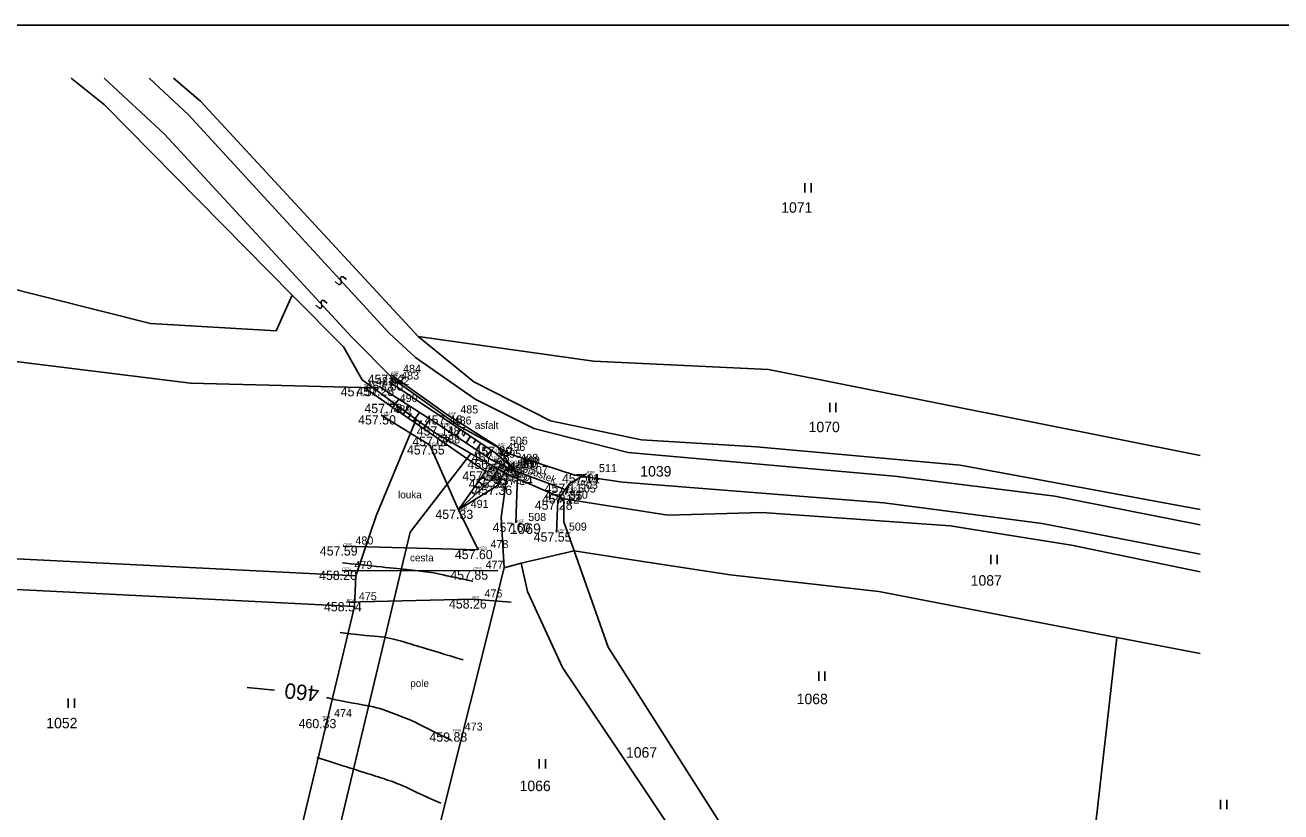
# Model space of a CAD drawing. Extents: x -604848 to -603227, y -1111879 to -1109838.
# Drawn here: x -603616.4 to -603412.5, y -1109965.7 to -1109837.9 of the extents above; entities that cross this region are included whole.
import ezdxf

# ---------------------------------------------------------------- set-up
doc = ezdxf.new("R2010")
doc.units = 0
for name, color, linetype in [('1', 7, 'Continuous'), ('10', 7, 'Continuous'), ('14', 7, 'Continuous'), ('18', 7, 'Continuous'), ('19', 7, 'Continuous'), ('2', 7, 'Continuous'), ('20', 7, 'Continuous'), ('23', 7, 'Continuous'), ('4', 7, 'Continuous'), ('7', 7, 'Continuous'), ('8', 7, 'Continuous'), ('9', 7, 'Continuous'), ('Default', 7, 'Continuous')]:
    doc.layers.add(name, color=color, linetype=linetype)

# ---------------------------------------------------------------- blocks, each defined once
blk = doc.blocks.new('Z3060')
at = {"layer": '23'}
for p, q in [((-0.5, 0), (-0.5, 1.5)), ((0.5, 1.5), (0.5, 0))]:
    blk.add_line(p, q, dxfattribs=at)
blk = doc.blocks.new('POINT_DISPLAY')
at = {"layer": 'Default'}
blk.add_line((0, 0), (0, 0), dxfattribs=at)
blk = doc.blocks.new('Z218')
at = {"layer": '2'}
for p, q in [((-0.2, 0.7), (-0.4, 0.5)), ((-0.4, 0.5), (-0.4, 0.3)), ((-0.4, 0.3), (-0.2, 0.1)), ((0.5, 0.8), (-0.2, 0.7)), ((-0.2, 0.1), (0.2, -0.1)), ((0.2, -0.7), (-0.5, -0.8)), ((0.2, -0.1), (0.4, -0.3)), ((0.4, -0.5), (0.2, -0.7)), ((0.4, -0.3), (0.4, -0.5))]:
    blk.add_line(p, q, dxfattribs=at)

msp = doc.modelspace()

# ---------------------------------------------------------------- linework, layer by layer
at = {"layer": '1'}
for p, q in [((-603603.52, -1109850.88), (-603608.9, -1109846.55)), ((-603592.28, -1109846.55), (-603587.91, -1109850.29)), ((-603573.01, -1109881.76), (-603603.52, -1109850.88)), ((-603587.91, -1109850.29), (-603552.55, -1109888.51)), ((-603633.29, -1109877.02), (-603596.04, -1109886.41)), ((-603575.63, -1109887.55), (-603573.01, -1109881.76)), ((-603564.71, -1109890.15), (-603573.01, -1109881.76)), ((-603589.52, -1109896.09), (-603686.95, -1109884.04)), ((-603596.04, -1109886.41), (-603575.63, -1109887.55)), ((-603561.66, -1109895.54), (-603564.71, -1109890.15)), ((-603552.55, -1109888.51), (-603524.1, -1109892.48)), ((-603543.5, -1109895.84), (-603552.55, -1109888.51)), ((-603524.1, -1109892.48), (-603495.66, -1109893.88)), ((-603495.66, -1109893.88), (-603425.58, -1109907.82)), ((-603559.88, -1109896.84), (-603589.52, -1109896.09)), ((-603559.88, -1109896.84), (-603561.66, -1109895.54)), ((-603531.07, -1109902.2), (-603543.5, -1109895.84)), ((-603552.87, -1109901.95), (-603559.88, -1109896.84)), ((-603559.39, -1109917.61), (-603552.87, -1109901.95)), ((-603549.91, -1109904.11), (-603552.87, -1109901.95)), ((-603516.27, -1109905.3), (-603531.07, -1109902.2)), ((-603544.01, -1109907.48), (-603549.91, -1109904.11)), ((-603497.64, -1109906.42), (-603516.27, -1109905.3)), ((-603464.54, -1109909.38), (-603497.64, -1109906.42)), ((-603553.85, -1109920.25), (-603544.01, -1109907.48)), ((-603544.01, -1109907.48), (-603538.11, -1109910.84)), ((-603425.58, -1109916.59), (-603464.54, -1109909.38)), ((-603538.11, -1109910.84), (-603539.09, -1109917.87)), ((-603538.11, -1109910.84), (-603528.91, -1109914.84)), ((-603512.03, -1109917.53), (-603528.91, -1109914.84)), ((-603528.91, -1109914.84), (-603528.91, -1109918.57)), ((-603562.66, -1109927.35), (-603559.39, -1109917.61)), ((-603539.09, -1109917.87), (-603538.61, -1109926.08)), ((-603528.91, -1109918.57), (-603527.23, -1109923.32)), ((-603496.72, -1109917.08), (-603512.03, -1109917.53)), ((-603466.14, -1109919.25), (-603496.72, -1109917.08)), ((-603575.13, -1110009.26), (-603553.85, -1109920.25)), ((-603446.47, -1109922.37), (-603466.14, -1109919.25)), ((-603425.58, -1109926.71), (-603446.47, -1109922.37)), ((-603648.55, -1109923.04), (-603562.66, -1109927.35)), ((-603535.85, -1109925.28), (-603527.23, -1109923.32)), ((-603527.23, -1109923.32), (-603519.62, -1109924.48)), ((-603527.23, -1109923.32), (-603521.7, -1109938.92)), ((-603519.62, -1109924.48), (-603501.91, -1109927.22)), ((-603550.44, -1109973.35), (-603538.61, -1109926.08)), ((-603538.61, -1109926.08), (-603535.85, -1109925.28)), ((-603534.83, -1109929.91), (-603535.85, -1109925.28)), ((-603648.86, -1109928.03), (-603562.91, -1109932.34)), ((-603562.66, -1109927.35), (-603562.91, -1109932.34)), ((-603501.91, -1109927.22), (-603477.74, -1109929.92)), ((-603529.1, -1109942.23), (-603534.83, -1109929.91)), ((-603477.74, -1109929.92), (-603439.12, -1109937.35)), ((-603562.91, -1109932.34), (-603571.51, -1109968.22)), ((-603521.7, -1109938.92), (-603496.72, -1109978.18)), ((-603439.12, -1109937.35), (-603445.06, -1109990.31)), ((-603425.58, -1109939.95), (-603439.12, -1109937.35)), ((-603515.89, -1109961.92), (-603529.1, -1109942.23)), ((-603502.69, -1109981.6), (-603515.89, -1109961.92))]:
    msp.add_line(p, q, dxfattribs=at)
msp.add_lwpolyline([(-603227.31, -1110677.93), (-603227.31, -1109837.93), (-603821.31, -1109837.93), (-603821.31, -1110677.93), (-603227.31, -1110677.93)], dxfattribs=at)
at = {"layer": '10'}
for p, q in [((-603558.56, -1109901.28), (-603550.66, -1109906.16)), ((-603550.66, -1109906.16), (-603546.03, -1109916.62)), ((-603546.03, -1109916.62), (-603542.81, -1109923.15)), ((-603543.79, -1109931.17), (-603564.19, -1109931.63)), ((-603543.79, -1109931.17), (-603537.46, -1109931.61))]:
    msp.add_line(p, q, dxfattribs=at)
at = {"layer": '2'}
for p, q in [((-603603.53, -1109846.55), (-603593.75, -1109855.63)), ((-603589.87, -1109852.5), (-603596.24, -1109846.55)), ((-603557.27, -1109887.93), (-603589.87, -1109852.5)), ((-603593.75, -1109855.63), (-603563.39, -1109888.55)), ((-603553.01, -1109891.89), (-603557.27, -1109887.93)), ((-603563.39, -1109888.55), (-603556.56, -1109895.4)), ((-603543.29, -1109898.66), (-603553.01, -1109891.89)), ((-603556.56, -1109895.4), (-603546, -1109902.98)), ((-603533.8, -1109903.43), (-603543.29, -1109898.66)), ((-603546, -1109902.98), (-603537.42, -1109907.68)), ((-603518.47, -1109907.32), (-603533.8, -1109903.43)), ((-603537.42, -1109907.68), (-603527.13, -1109911)), ((-603475.23, -1109911.19), (-603518.47, -1109907.32)), ((-603527.13, -1109911), (-603519.35, -1109912.17)), ((-603519.35, -1109912.17), (-603476.94, -1109915.52)), ((-603449.19, -1109914.4), (-603475.23, -1109911.19)), ((-603425.58, -1109919.06), (-603449.19, -1109914.4)), ((-603476.94, -1109915.52), (-603451.22, -1109918.85)), ((-603451.22, -1109918.85), (-603425.58, -1109923.86))]:
    msp.add_line(p, q, dxfattribs=at)
at = {"layer": '4'}
for p, q in [((-603547.72, -1109901.29), (-603557.01, -1109894.68)), ((-603539.67, -1109906.36), (-603547.72, -1109901.29)), ((-603536.41, -1109911.12), (-603539.67, -1109906.36)), ((-603537.97, -1109910.25), (-603538.48, -1109910.22)), ((-603537.97, -1109909.17), (-603537.68, -1109909.57)), ((-603537.68, -1109909.57), (-603537.97, -1109910.25)), ((-603537.87, -1109909.92), (-603528.27, -1109913.52)), ((-603536.68, -1109918.75), (-603536.41, -1109911.12)), ((-603529.9, -1109915.13), (-603528.03, -1109912.4)), ((-603528.63, -1109914.14), (-603528.03, -1109912.4)), ((-603528.03, -1109912.4), (-603525.2, -1109910.82)), ((-603530.08, -1109920.31), (-603529.9, -1109915.13)), ((-603542.81, -1109923.15), (-603564.75, -1109922.57)), ((-603564.91, -1109926.53), (-603543.61, -1109926.49)), ((-603543.61, -1109926.49), (-603539.6, -1109926.56))]:
    msp.add_line(p, q, dxfattribs=at)
at = {"layer": '7'}
for p, q in [((-603557.32, -1109895.78), (-603540.06, -1109907.38)), ((-603557.55, -1109899.43), (-603561.4, -1109896.7)), ((-603558.88, -1109896.63), (-603548.79, -1109903.09)), ((-603549.76, -1109904.78), (-603557.55, -1109899.43)), ((-603548.79, -1109903.09), (-603540.74, -1109908.49)), ((-603541.62, -1109910.41), (-603549.76, -1109904.78)), ((-603540.74, -1109908.49), (-603537.87, -1109909.92)), ((-603537.97, -1109909.17), (-603540.06, -1109907.38)), ((-603546.03, -1109916.62), (-603541.62, -1109910.41)), ((-603540.54, -1109911.64), (-603539.15, -1109909.28)), ((-603538.55, -1109910.47), (-603539.65, -1109912.71)), ((-603538.48, -1109910.22), (-603538.55, -1109910.47)), ((-603546.03, -1109916.62), (-603540.54, -1109911.64)), ((-603539.65, -1109912.71), (-603546.03, -1109916.62)), ((-603575.87, -1109945.94), (-603580.35, -1109945.5))]:
    msp.add_line(p, q, dxfattribs=at)
for points in [[(-603543.68, -1109928.2), (-603546.74, -1109927.64), (-603549.77, -1109926.84), (-603552.87, -1109926.51), (-603556.87, -1109926.09), (-603560.86, -1109925.67), (-603564.86, -1109925.25)], [(-603545.24, -1109941.01), (-603548.45, -1109940.05), (-603551.59, -1109939.08), (-603554.85, -1109938.11), (-603558.25, -1109937.1), (-603561.77, -1109937.06), (-603565.23, -1109936.54)], [(-603547.19, -1109954.02), (-603550.29, -1109952.58), (-603553.28, -1109950.92), (-603556.5, -1109949.72), (-603560.04, -1109948.41), (-603563.82, -1109948), (-603567.47, -1109947.13)], [(-603548.86, -1109964.27), (-603552.11, -1109962.9), (-603555.26, -1109961.23), (-603558.62, -1109960.16), (-603562.09, -1109959.05), (-603565.55, -1109957.95), (-603569.02, -1109956.84)]]:
    msp.add_open_spline(points, degree=3, dxfattribs=at)
at = {"layer": '8'}
for p, q in [((-603556.65, -1109900.05), (-603555.7, -1109898.66)), ((-603555.83, -1109900.62), (-603555.34, -1109899.91)), ((-603555, -1109901.18), (-603554.02, -1109899.74)), ((-603554.18, -1109901.75), (-603553.68, -1109901.02)), ((-603553.35, -1109902.31), (-603552.33, -1109900.82)), ((-603552.53, -1109902.88), (-603552.01, -1109902.12)), ((-603551.7, -1109903.45), (-603550.65, -1109901.9)), ((-603545.71, -1109903.59), (-603546.43, -1109904.67)), ((-603544.88, -1109904.15), (-603545.24, -1109904.69)), ((-603544.05, -1109904.7), (-603544.77, -1109905.78)), ((-603543.22, -1109905.26), (-603543.58, -1109905.8)), ((-603542.39, -1109905.82), (-603543.11, -1109906.9)), ((-603541.56, -1109906.38), (-603541.92, -1109906.92)), ((-603540.73, -1109906.94), (-603541.45, -1109908.01)), ((-603542.78, -1109912.04), (-603541.77, -1109912.76)), ((-603542.2, -1109911.23), (-603541.61, -1109911.65)), ((-603543.94, -1109913.67), (-603543.29, -1109914.14)), ((-603543.36, -1109912.86), (-603542.94, -1109913.15))]:
    msp.add_line(p, q, dxfattribs=at)

# ---------------------------------------------------------------- block references
at = {"layer": '18'}
for p in [(-603557.32, -1109895.78), (-603557.01, -1109894.68), (-603561.4, -1109896.7), (-603558.88, -1109896.63), (-603557.55, -1109899.43), (-603558.56, -1109901.28), (-603547.72, -1109901.29), (-603548.79, -1109903.09), (-603550.66, -1109906.16), (-603549.76, -1109904.78), (-603539.67, -1109906.36), (-603540.74, -1109908.49), (-603540.06, -1109907.38), (-603541.62, -1109910.41), (-603538.55, -1109910.47), (-603538.48, -1109910.22), (-603537.97, -1109909.17), (-603537.97, -1109910.25), (-603537.87, -1109909.92), (-603537.68, -1109909.57), (-603540.54, -1109911.64), (-603539.65, -1109912.71), (-603536.41, -1109911.12), (-603528.03, -1109912.4), (-603525.2, -1109910.82), (-603528.63, -1109914.14), (-603528.27, -1109913.52), (-603546.03, -1109916.62), (-603529.9, -1109915.13), (-603536.68, -1109918.75), (-603530.08, -1109920.31), (-603564.75, -1109922.57), (-603542.81, -1109923.15), (-603564.91, -1109926.53), (-603543.61, -1109926.49), (-603543.79, -1109931.17), (-603564.19, -1109931.63), (-603568.21, -1109950.6), (-603546.99, -1109952.79)]:
    msp.add_blockref('POINT_DISPLAY', p, dxfattribs=at)
at = {"layer": '2'}
for p, xscale, yscale, rotation in [((-603565.11, -1109879.41), 0.9999962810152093, 0.9999962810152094, 132.6180458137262), ((-603568.27, -1109883.26), 0.9999956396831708, 0.9999956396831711, -47.316624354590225)]:
    msp.add_blockref('Z218', p, dxfattribs=dict(at, xscale=xscale, yscale=yscale, rotation=rotation))
at = {"layer": '23'}
for p in [(-603489.26, -1109865.12), (-603485.21, -1109900.76), (-603459.06, -1109925.45), (-603487, -1109944.41), (-603608.89, -1109948.8), (-603532.39, -1109958.65), (-603421.74, -1109965.26)]:
    msp.add_blockref('Z3060', p, dxfattribs=at)

# ---------------------------------------------------------------- texts
at = {"layer": '14'}
for s, p in [('1071', (-603493.6, -1109868.4)), ('1070', (-603489.15, -1109904.03)), ('1039', (-603516.49, -1109911.24)), ('1069', (-603537.69, -1109920.56)), ('1087', (-603462.83, -1109928.96)), ('1068', (-603491.09, -1109948.2)), ('1052', (-603612.95, -1109952.12)), ('1067', (-603518.81, -1109956.89)), ('1066', (-603536.09, -1109962.32))]:
    msp.add_text(s, height=1.7, dxfattribs=at).set_placement(p)
at = {"layer": '18'}
for s, p in [('ASF', (-603557.01, -1109894.68)), ('TER', (-603561.4, -1109896.7)), ('TER', (-603558.88, -1109896.63)), ('TER', (-603557.32, -1109895.78)), ('TER', (-603557.55, -1109899.43)), ('LOU', (-603558.56, -1109901.28)), ('TER', (-603548.79, -1109903.09)), ('ASF', (-603547.72, -1109901.29)), ('TER', (-603549.76, -1109904.78)), ('LOU', (-603550.66, -1109906.16)), ('ASF', (-603539.67, -1109906.36)), ('TER', (-603540.74, -1109908.49)), ('TER', (-603540.06, -1109907.38)), ('PRO', (-603537.97, -1109909.17)), ('TER', (-603541.62, -1109910.41)), ('TER', (-603538.55, -1109910.47)), ('PRO', (-603538.48, -1109910.22)), ('PRO', (-603537.97, -1109910.25)), ('PRO', (-603537.87, -1109909.92)), ('PRO', (-603537.68, -1109909.57)), ('ASF', (-603536.41, -1109911.12)), ('ASF', (-603525.2, -1109910.82)), ('TER', (-603540.54, -1109911.64)), ('TER', (-603539.65, -1109912.71)), ('PRO', (-603528.03, -1109912.4)), ('ASF', (-603529.9, -1109915.13)), ('PRO', (-603528.63, -1109914.14)), ('PRO', (-603528.27, -1109913.52)), ('TER', (-603546.03, -1109916.62)), ('ASF', (-603536.68, -1109918.75)), ('ASF', (-603530.08, -1109920.31)), ('CES', (-603564.75, -1109922.57)), ('CES', (-603542.81, -1109923.15)), ('CES', (-603564.91, -1109926.53)), ('CES', (-603543.61, -1109926.49)), ('POL', (-603564.19, -1109931.63)), ('POL', (-603543.79, -1109931.17)), ('TER', (-603568.21, -1109950.6)), ('TER', (-603546.99, -1109952.79))]:
    msp.add_text(s, height=0.5, dxfattribs=at).set_placement(p)
at = {"layer": '19'}
for s, p in [('483', (-603555.32, -1109895.48)), ('484', (-603555.01, -1109894.38)), ('481', (-603559.4, -1109896.4)), ('482', (-603556.88, -1109896.33)), ('490', (-603555.55, -1109899.13)), ('489', (-603556.56, -1109900.98)), ('485', (-603545.72, -1109900.99)), ('486', (-603546.79, -1109902.79)), ('488', (-603548.66, -1109905.86)), ('487', (-603547.76, -1109904.48)), ('496', (-603538.06, -1109907.08)), ('506', (-603537.67, -1109906.06)), ('495', (-603538.74, -1109908.19)), ('501', (-603536.48, -1109909.92)), ('498', (-603535.97, -1109908.86)), ('500', (-603535.97, -1109909.95)), ('497', (-603535.87, -1109909.62)), ('499', (-603535.68, -1109909.27)), ('494', (-603539.62, -1109910.11)), ('492', (-603538.54, -1109911.34)), ('502', (-603536.55, -1109910.17)), ('507', (-603534.41, -1109910.82)), ('504', (-603526.03, -1109912.1)), ('511', (-603523.2, -1109910.52)), ('493', (-603537.65, -1109912.42)), ('505', (-603526.63, -1109913.84)), ('503', (-603526.27, -1109913.22)), ('510', (-603527.9, -1109914.83)), ('491', (-603544.03, -1109916.32)), ('508', (-603534.68, -1109918.45)), ('509', (-603528.08, -1109920.01)), ('480', (-603562.75, -1109922.27)), ('478', (-603540.81, -1109922.85)), ('479', (-603562.91, -1109926.23)), ('477', (-603541.61, -1109926.2)), ('475', (-603562.19, -1109931.33)), ('476', (-603541.79, -1109930.87)), ('474', (-603566.21, -1109950.3)), ('473', (-603544.99, -1109952.49))]:
    msp.add_text(s, height=1.3, dxfattribs=at).set_placement(p)
at = {"layer": '20'}
for s, p in [('457.60 ', (-603561.11, -1109897.28)), ('457.62 ', (-603560.76, -1109896.18)), ('457.57 ', (-603565.13, -1109898.2)), ('457.28 ', (-603562.6, -1109898.13)), ('457.78 ', (-603561.29, -1109900.93)), ('457.50 ', (-603562.31, -1109902.78)), ('457.46 ', (-603551.49, -1109902.79)), ('457.11 ', (-603552.79, -1109904.59)), ('457.55 ', (-603554.39, -1109907.66)), ('457.62 ', (-603553.52, -1109906.28)), ('457.30 ', (-603543.42, -1109907.86)), ('456.79 ', (-603544.56, -1109909.99)), ('457.26 ', (-603543.85, -1109908.88)), ('457.56 ', (-603545.4, -1109911.91)), ('457.35 ', (-603542.28, -1109911.97)), ('457.34 ', (-603542.16, -1109911.72)), ('457.15 ', (-603541.79, -1109910.67)), ('457.40 ', (-603541.71, -1109911.75)), ('456.62 ', (-603541.66, -1109911.42)), ('457.36 ', (-603541.46, -1109911.07)), ('456.89 ', (-603544.34, -1109913.14)), ('457.36 ', (-603543.43, -1109914.21)), ('457.34 ', (-603540.09, -1109912.62)), ('457.11 ', (-603532.03, -1109913.9)), ('457.11 ', (-603529.2, -1109912.32)), ('457.12 ', (-603532.45, -1109915.64)), ('456.35 ', (-603532.02, -1109915.02)), ('457.33 ', (-603549.76, -1109918.12)), ('457.28 ', (-603533.62, -1109916.63)), ('457.60 ', (-603540.47, -1109920.25)), ('457.55 ', (-603533.8, -1109921.81)), ('457.59 ', (-603568.53, -1109924.07)), ('457.60 ', (-603546.6, -1109924.65)), ('458.20 ', (-603568.65, -1109928.03)), ('457.85 ', (-603547.34, -1109927.99)), ('458.26 ', (-603547.56, -1109932.67)), ('458.54 ', (-603567.86, -1109933.13)), ('460.33 ', (-603571.98, -1109952.1)), ('459.88 ', (-603550.73, -1109954.29))]:
    msp.add_text(s, height=1.5, dxfattribs=at).set_placement(p)
at = {"layer": '7'}
msp.add_text('460', height=2.5, rotation=173.7, dxfattribs=at).set_placement((-603568.56, -1109945.35))
at = {"layer": '9'}
for s, p in [('asfalt', (-603543.36, -1109903.5)), ('louka', (-603555.82, -1109914.77)), ('cesta', (-603553.88, -1109925.01)), ('pole', (-603553.84, -1109945.41))]:
    msp.add_text(s, height=1.2, dxfattribs=at).set_placement(p)
msp.add_text('propustek', height=1.2, rotation=339.3, dxfattribs=at).set_placement((-603537, -1109909.9))

doc.saveas('drawing.dxf')
